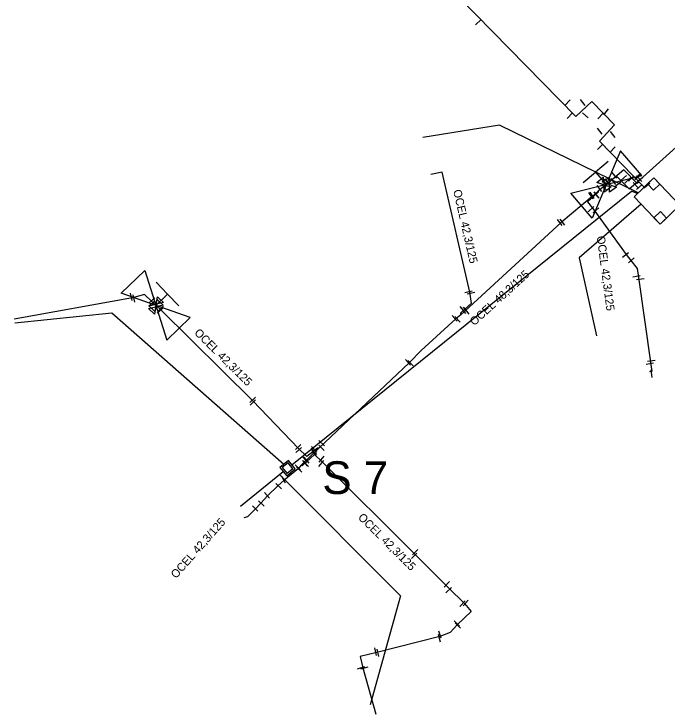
# Model space of a CAD drawing. Extents: x -642943 to -623314, y -1138561 to -1113539.
# Drawn here: x -642363.4 to -642303.4, y -1114769.7 to -1114705.5 of the extents above; entities that cross this region are included whole.
import ezdxf

# ---------------------------------------------------------------- set-up
doc = ezdxf.new("R2010")
doc.units = 0
for name, color, linetype in [('horkovod armatury', 7, 'Continuous'), ('horkovod dimenze', 7, 'Continuous'), ('horkovod předisol', 7, 'Continuous'), ('horkovod sváry', 7, 'Continuous'), ('horkovod trasa', 7, 'Continuous'), ('horkovod zrušený', 7, 'Continuous'), ('horkovod číslo šachty', 7, 'Continuous'), ('horkovod šachty', 7, 'Continuous')]:
    doc.layers.add(name, color=color, linetype=linetype)

# ---------------------------------------------------------------- blocks, each defined once
blk = doc.blocks.new('SPH_2')
at = {"layer": 'horkovod sváry'}
blk.add_line((-0.0001, -0.0349), (0.0001, 0.0349), dxfattribs=at)
blk = doc.blocks.new('SPH_1')
at = {"layer": 'horkovod sváry'}
blk.add_line((0.0001, -0.035), (-0.0001, 0.035), dxfattribs=at)
blk = doc.blocks.new('SPH')
at = {"layer": 'horkovod sváry'}
blk.add_line((0, -0.035), (0, 0.035), dxfattribs=at)
blk = doc.blocks.new('POINT_DISPLAY')
blk.add_line((0, 0), (0, 0))
blk = doc.blocks.new('SH')
at = {"layer": 'horkovod armatury'}
for p, q in [((-0.0568, -0.0385), (-0.0564, 0.0379)), ((-0.0564, 0.0379), (0, 0)), ((0.0007, -0.0004), (0.0582, 0.0375)), ((0.0582, 0.0375), (0.0581, -0.0389)), ((0.0007, -0.0004), (-0.0568, -0.0385)), ((0.0581, -0.0389), (0.0007, -0.0004))]:
    blk.add_line(p, q, dxfattribs=at)
blk = doc.blocks.new('SCH_01_109')
at = {"layer": 'horkovod armatury'}
for p, q in [((10, 5), (-10, -5)), ((-10, -5), (-10, 5)), ((-10, 5), (10, -5)), ((-5, 5), (0, 5)), ((0, 5), (0, 0)), ((5, 5), (0, 5)), ((10, -5), (10, 5))]:
    blk.add_line(p, q, dxfattribs=at)

msp = doc.modelspace()

# ---------------------------------------------------------------- linework, layer by layer
at = {"layer": 'horkovod předisol'}
for p, q in [((-642335.423, -1114690.871), (-642311.877, -1114714.932)), ((-642310.439, -1114713.537), (-642311.877, -1114714.932)), ((-642310.439, -1114713.537), (-642308.35, -1114715.667)), ((-642308.35, -1114715.667), (-642309.71, -1114717.178)), ((-642309.71, -1114717.178), (-642305.643, -1114721.406)), ((-642335.418, -1114745.319), (-642337.045, -1114746.875))]:
    msp.add_line(p, q, dxfattribs=at)
for points in [[(-642308.17, -1114720.391), (-642306.992, -1114721.546), (-642305.755, -1114720.476), (-642302.077, -1114717.169), (-642301.275, -1114716.574), (-642300.333, -1114716.204), (-642298.928, -1114715.605), (-642292.818, -1114713.4)], [(-642322.435, -1114733.08), (-642322.435, -1114732.922), (-642321.439, -1114732.033), (-642321.608, -1114731.022), (-642324.13, -1114720.017), (-642325.177, -1114720.242)], [(-642306.107, -1114720.923), (-642306.271, -1114721.062), (-642307.489, -1114719.816), (-642308.919, -1114721.023), (-642309.354, -1114721.357), (-642309.837, -1114721.774)], [(-642309.837, -1114721.774), (-642310.397, -1114722.253), (-642313.246, -1114724.635), (-642322.435, -1114733.08)], [(-642309.837, -1114721.774), (-642309.848, -1114721.858), (-642310.827, -1114722.742), (-642310.249, -1114723.479), (-642307.277, -1114727.559), (-642306.845, -1114728.129), (-642306.263, -1114728.839), (-642306.148, -1114729.669), (-642305.04, -1114737.434), (-642304.919, -1114738.282), (-642305.151, -1114738.315)], [(-642335.418, -1114745.319), (-642335.547, -1114745.319), (-642336.534, -1114746.077), (-642337.306, -1114745.334), (-642341.49, -1114740.989), (-642349.936, -1114732.617), (-642350.735, -1114731.885), (-642351.395, -1114731.233), (-642352.496, -1114731.53), (-642363.352, -1114733.479)], [(-642322.435, -1114733.08), (-642322.887, -1114733.472), (-642326.048, -1114736.35), (-642327.142, -1114737.495), (-642335.418, -1114745.319)], [(-642337.045, -1114746.875), (-642336.938, -1114746.893), (-642335.831, -1114745.901), (-642335.162, -1114746.535), (-642326.636, -1114755.033), (-642323.54, -1114758.119), (-642322.101, -1114759.553), (-642321.476, -1114760.281), (-642322.736, -1114761.475), (-642323.406, -1114762.221), (-642324.343, -1114762.58), (-642330.13, -1114764.032), (-642331.637, -1114764.412), (-642331.393, -1114765.439), (-642330.208, -1114769.678)], [(-642337.045, -1114746.875), (-642337.285, -1114747.182), (-642338.629, -1114748.271), (-642339.162, -1114748.745), (-642340.122, -1114749.694), (-642340.736, -1114750.343), (-642341.218, -1114750.873), (-642341.953, -1114751.6), (-642342.307, -1114751.702)]]:
    msp.add_lwpolyline(points, dxfattribs=at)
at = {"layer": 'horkovod trasa'}
for p, q in [((-642335.423, -1114690.871), (-642311.877, -1114714.932)), ((-642310.439, -1114713.537), (-642311.877, -1114714.932)), ((-642310.439, -1114713.537), (-642308.35, -1114715.667)), ((-642308.35, -1114715.667), (-642309.71, -1114717.178)), ((-642309.71, -1114717.178), (-642305.643, -1114721.406)), ((-642335.418, -1114745.319), (-642337.045, -1114746.875))]:
    msp.add_line(p, q, dxfattribs=at)
for points in [[(-642308.17, -1114720.391), (-642306.992, -1114721.546), (-642305.755, -1114720.476), (-642302.077, -1114717.169), (-642301.275, -1114716.574), (-642300.333, -1114716.204), (-642298.928, -1114715.605), (-642292.818, -1114713.4)], [(-642322.435, -1114733.08), (-642322.435, -1114732.922), (-642321.439, -1114732.033), (-642321.608, -1114731.022), (-642324.13, -1114720.017), (-642325.177, -1114720.242)], [(-642306.107, -1114720.923), (-642306.271, -1114721.062), (-642307.489, -1114719.816), (-642308.919, -1114721.023), (-642309.354, -1114721.357), (-642309.837, -1114721.774)], [(-642309.837, -1114721.774), (-642310.397, -1114722.253), (-642313.246, -1114724.635), (-642322.435, -1114733.08)], [(-642309.837, -1114721.774), (-642309.848, -1114721.858), (-642310.827, -1114722.742), (-642310.249, -1114723.479), (-642307.277, -1114727.559), (-642306.845, -1114728.129), (-642306.263, -1114728.839), (-642306.148, -1114729.669), (-642305.04, -1114737.434), (-642304.919, -1114738.282), (-642305.151, -1114738.315)], [(-642335.418, -1114745.319), (-642335.547, -1114745.319), (-642336.534, -1114746.077), (-642337.306, -1114745.334), (-642341.49, -1114740.989), (-642349.936, -1114732.617), (-642350.735, -1114731.885), (-642351.395, -1114731.233), (-642352.496, -1114731.53), (-642363.352, -1114733.479)], [(-642322.435, -1114733.08), (-642322.887, -1114733.472), (-642326.048, -1114736.35), (-642327.142, -1114737.495), (-642335.418, -1114745.319)], [(-642337.045, -1114746.875), (-642336.938, -1114746.893), (-642335.831, -1114745.901), (-642335.162, -1114746.535), (-642326.636, -1114755.033), (-642323.54, -1114758.119), (-642322.101, -1114759.553), (-642321.476, -1114760.281), (-642322.736, -1114761.475), (-642323.406, -1114762.221), (-642324.343, -1114762.58), (-642330.13, -1114764.032), (-642331.637, -1114764.412), (-642331.393, -1114765.439), (-642330.208, -1114769.678)], [(-642337.045, -1114746.875), (-642337.285, -1114747.182), (-642338.629, -1114748.271), (-642339.162, -1114748.745), (-642340.122, -1114749.694), (-642340.736, -1114750.343), (-642341.218, -1114750.873), (-642341.953, -1114751.6), (-642342.307, -1114751.702)]]:
    msp.add_lwpolyline(points, dxfattribs=at)
at = {"layer": 'horkovod zrušený'}
for p, q in [((-642318.867, -1114715.712), (-642325.9, -1114716.855)), ((-642306.191, -1114721.924), (-642318.867, -1114715.712)), ((-642337.91, -1114746.834), (-642306.789, -1114721.749)), ((-642306.257, -1114721.988), (-642306.789, -1114721.749)), ((-642342.614, -1114750.633), (-642338.685, -1114747.465)), ((-642327.936, -1114758.86), (-642339.028, -1114747.742)), ((-642327.936, -1114758.86), (-642330.721, -1114768.834))]:
    msp.add_line(p, q, dxfattribs=at)
for points in [[(-642305.918, -1114722.952), (-642311.597, -1114727.865), (-642309.985, -1114735.005)], [(-642363.268, -1114733.835), (-642354.383, -1114732.908), (-642338.63, -1114746.776)]]:
    msp.add_lwpolyline(points, dxfattribs=at)
at = {"layer": 'horkovod šachty'}
for p, q in [((-642304.735, -1114720.547), (-642305.316, -1114721.097)), ((-642304.185, -1114721.128), (-642304.735, -1114720.547)), ((-642305.316, -1114721.097), (-642304.766, -1114721.678)), ((-642304.766, -1114721.678), (-642304.185, -1114721.128)), ((-642304.15, -1114723.639), (-642304.731, -1114724.191)), ((-642303.599, -1114724.22), (-642304.15, -1114723.639)), ((-642304.731, -1114724.191), (-642304.179, -1114724.771)), ((-642303.599, -1114724.22), (-642304.179, -1114724.771)), ((-642338.24, -1114746.656), (-642338.784, -1114747.096)), ((-642337.8, -1114747.2), (-642338.24, -1114746.656)), ((-642338.784, -1114747.096), (-642338.344, -1114747.64)), ((-642337.8, -1114747.2), (-642338.344, -1114747.64))]:
    msp.add_line(p, q, dxfattribs=at)
for points in [[(-642306.551, -1114722.266), (-642304.179, -1114724.771), (-642302.363, -1114723.052), (-642304.735, -1114720.547), (-642306.551, -1114722.266)], [(-642339.002, -1114747.073), (-642338.374, -1114747.851), (-642337.596, -1114747.223), (-642338.224, -1114746.445), (-642339.002, -1114747.073)]]:
    msp.add_lwpolyline(points, dxfattribs=at)

# ---------------------------------------------------------------- block references
at = {"layer": 'horkovod armatury'}
for name, p, xscale, yscale, rotation in [('SCH_01_109', (-642309.102, -1114721.144), 0.29998715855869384, 0.29998715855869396, 40.60257967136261), ('SH', (-642309.32, -1114721.16), 9.9999986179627, 9.9999986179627, -50.46904901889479), ('SH', (-642308.82, -1114721.15), 10.000000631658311, 10.000000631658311, -54.431741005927), ('SCH_01_109', (-642350.362, -1114732.228), 0.2999871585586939, 0.2999871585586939, -46.15509971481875), ('SH', (-642350.331, -1114732.117), 10.000000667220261, 10.00000066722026, 45.99239812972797), ('SH', (-642350.37, -1114732.37), 10.000013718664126, 10.000013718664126, 47.00510154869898)]:
    msp.add_blockref(name, p, dxfattribs=dict(at, xscale=xscale, yscale=yscale, rotation=rotation))
at = {"layer": 'horkovod sváry'}
for name, p, xscale, yscale, rotation in [('SPH_2', (-642320.83, -1114706.27), 10.000023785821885, 10.000023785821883, -46.93544318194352), ('SPH_2', (-642312.66, -1114713.65), 10.000015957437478, 10.000015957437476, -44.32590539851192), ('SPH_2', (-642311.25, -1114713.64), 9.99998312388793, 9.99998312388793, 38.360172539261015), ('SPH_2', (-642309.11, -1114714.48), 9.99999901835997, 9.999999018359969, -38.7285186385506), ('SPH_2', (-642312.44, -1114714.84), 10.00001530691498, 10.00001530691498, -41.54185407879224), ('SPH_2', (-642311.02, -1114714.81), 10.000009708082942, 10.000009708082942, 47.55888123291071), ('SPH_1', (-642309.63, -1114714.86), 9.999987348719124, 9.999987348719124, -42.8482080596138), ('SPH_2', (-642309.69, -1114716.26), 9.999994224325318, 9.999994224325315, 38.69947611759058), ('SPH', (-642308.5, -1114716.58), 9.999973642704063, 9.999973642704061, 38.324837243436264), ('SPH_2', (-642309.67, -1114717.69), 10.000012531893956, 10.000012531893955, -44.709086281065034), ('SPH_1', (-642308.53, -1114717.95), 10.000004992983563, 10.000004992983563, -42.79100666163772), ('SPH_2', (-642308.35, -1114720.3), 9.999996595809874, 9.999996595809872, 40.754295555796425), ('SPH_2', (-642309.01, -1114720.91), 9.999967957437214, 9.999967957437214, 38.46784328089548), ('SPH_2', (-642308.45, -1114720.87), 9.999978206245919, 9.999978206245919, 38.945776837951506), ('SPH_2', (-642307.51, -1114720.55), 10.00001452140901, 10.00001452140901, -49.06486324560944), ('SPH_1', (-642307.15, -1114720.79), 10.00000385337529, 10.000003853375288, -47.21371358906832), ('SPH_2', (-642306.82, -1114720.61), 9.999989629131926, 9.999989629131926, -45.39505637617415), ('SPH_2', (-642306.22, -1114720.36), 10.000015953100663, 10.000015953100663, -48.83774303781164), ('SPH_2', (-642306.22, -1114720.48), 10.000005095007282, 10.00000509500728, -48.71069255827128), ('SPH_2', (-642306.1, -1114720.62), 9.999991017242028, 9.999991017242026, 44.06703707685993), ('SPH_2', (-642309.72, -1114721.52), 10.000023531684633, 10.000023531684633, 37.016746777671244), ('SPH_2', (-642309.28, -1114721.44), 10.000001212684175, 10.000001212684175, 39.95495661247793), ('SPH_2', (-642308.04, -1114721.12), 10.000005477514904, 10.000005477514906, -49.21827027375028), ('SPH', (-642306.4, -1114721.23), 9.999984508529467, 9.999984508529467, 42.14080740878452), ('SPH_2', (-642306.07, -1114721.39), 9.99999073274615, 9.99999073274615, -48.4993581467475), ('SPH_2', (-642305.38, -1114721.25), 10.000020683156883, 10.000020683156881, -48.15446315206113), ('SPH', (-642310.5, -1114722.17), 9.999991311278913, 9.999991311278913, 33.90111137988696), ('SPH_2', (-642310.39, -1114722.15), 9.999998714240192, 9.999998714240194, 32.89885229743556), ('SPH_2', (-642310, -1114722.11), 9.999985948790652, 9.999985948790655, 37.971603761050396), ('SPH_2', (-642309.97, -1114722.14), 9.999987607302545, 9.999987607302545, 39.00819611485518), ('SPH_2', (-642310.5, -1114723.41), 10.00000497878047, 10.000004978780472, -46.81690519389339), ('SPH_1', (-642310.05, -1114723.52), 9.999983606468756, 9.999983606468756, -49.64630891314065), ('SPH_2', (-642313.35, -1114724.64), 9.999985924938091, 9.999985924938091, 39.94737309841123), ('SPH_2', (-642313.11, -1114724.61), 9.999981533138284, 9.999981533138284, 39.52999399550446), ('SPH_2', (-642307.33, -1114727.6), 10.00001117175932, 10.00001117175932, -50.95138605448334), ('SPH_1', (-642306.81, -1114728.1), 9.999997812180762, 9.999997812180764, -50.932426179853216), ('SPH_2', (-642306.34, -1114729.54), 9.999991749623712, 9.999991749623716, -80.1902849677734), ('SPH_2', (-642305.99, -1114729.81), 10.000014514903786, 10.000014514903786, -81.77986946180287), ('SPH_2', (-642321.72, -1114730.98), 9.999999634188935, 9.999999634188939, -76.87367718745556), ('SPH_2', (-642352.61, -1114731.44), 10.000004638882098, 10.000004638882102, 11.242852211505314), ('SPH_2', (-642352.36, -1114731.6), 10.000014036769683, 10.000014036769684, 12.171437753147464), ('SPH_1', (-642350.72, -1114731.77), 9.999984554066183, 9.999984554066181, -48.11271832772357), ('SPH_2', (-642321.49, -1114731.1), 9.999983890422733, 9.999983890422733, -77.93740603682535), ('SPH_2', (-642350.73, -1114732.03), 10.000009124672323, 10.00000912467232, -48.85684328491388), ('SPH_2', (-642349.99, -1114732.72), 9.999990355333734, 9.999990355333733, -47.60251080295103), ('SPH_2', (-642349.9, -1114732.52), 10.000007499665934, 10.000007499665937, -46.4237694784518), ('SPH_1', (-642322.26, -1114732.6), 10.000021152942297, 10.000021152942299, 39.28946317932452), ('SPH_2', (-642322.19, -1114732.7), 9.99999825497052, 9.999998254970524, 38.36758997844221), ('SPH_2', (-642321.97, -1114732.65), 9.999991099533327, 9.999991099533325, 38.77747858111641), ('SPH_2', (-642321.88, -1114732.75), 9.9999906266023, 9.999990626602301, 38.422092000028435), ('SPH_1', (-642322.99, -1114733.42), 10.000014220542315, 10.000014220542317, 42.81423085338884), ('SPH_2', (-642322.74, -1114733.5), 10.00000659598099, 10.000006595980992, 43.780980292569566), ('SPH_1', (-642327.27, -1114737.46), 10.000000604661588, 10.000000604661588, 42.5370475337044), ('SPH_2', (-642327.02, -1114737.52), 10.000009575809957, 10.000009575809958, 44.47344463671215), ('SPH_2', (-642304.98, -1114737.286), 10.000014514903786, 10.000014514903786, -81.77986946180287), ('SPH_2', (-642305.118, -1114737.561), 9.999991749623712, 9.999991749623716, -80.1902849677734), ('SPH_2', (-642304.969, -1114738.491), 9.999996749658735, 9.999996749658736, -170.8897638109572), ('SPH_2', (-642341.49, -1114740.88), 9.999984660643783, 9.999984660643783, -45.39090596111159), ('SPH_2', (-642341.47, -1114741.12), 9.999987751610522, 9.999987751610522, -44.02288427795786), ('SPH_2', (-642337.32, -1114745.21), 9.999991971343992, 9.99999197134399, -46.39716262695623), ('SPH_2', (-642335.18, -1114745.27), 10.00000694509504, 10.000006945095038, 45.915225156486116), ('SPH_2', (-642335.16, -1114744.86), 9.999999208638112, 9.999999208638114, 47.93550435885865), ('SPH_2', (-642337.28, -1114745.49), 10.000002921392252, 10.000002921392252, -47.950615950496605), ('SPH_2', (-642335.89, -1114745.57), 10.000000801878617, 10.000000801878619, 43.32635303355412), ('SPH_2', (-642335.88, -1114745.7), 10.000000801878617, 10.000000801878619, 43.32635303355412), ('SPH_2', (-642335.86, -1114745.43), 10.000019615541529, 10.000019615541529, 41.91147635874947), ('SPH', (-642335.83, -1114745.88), 9.999996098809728, 9.999996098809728, 42.8619917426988), ('SPH_2', (-642336.69, -1114746.32), 10.000019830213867, 10.000019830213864, 40.507387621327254), ('SPH_1', (-642336.55, -1114746.41), 10.000001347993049, 10.000001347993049, 40.601236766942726), ('SPH_2', (-642335.16, -1114746.32), 9.999988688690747, 9.999988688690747, -40.958578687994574), ('SPH_2', (-642337.35, -1114747.09), 9.999979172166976, 9.999979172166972, 44.8603915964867), ('SPH_1', (-642336.7, -1114746.69), 10.000018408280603, 10.000018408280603, 41.8595179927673), ('SPH_1', (-642336.628, -1114746.741), 10.000004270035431, 10.000004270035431, 42.211268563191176), ('SPH_2', (-642335.19, -1114746.72), 9.999978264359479, 9.99997826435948, -40.75826050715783), ('SPH_2', (-642337.22, -1114747.26), 10.000001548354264, 10.000001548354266, 44.569286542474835), ('SPH_2', (-642338.656, -1114748.218), 10.000015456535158, 10.00001545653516, 27.44684979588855), ('SPH_2', (-642339.11, -1114748.8), 10.000002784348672, 10.000002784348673, 44.884351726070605), ('SPH_2', (-642340.18, -1114749.63), 10.000002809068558, 10.000002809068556, 42.43356307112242), ('SPH_2', (-642340.7, -1114750.38), 10.00000446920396, 10.000004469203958, 45.563157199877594), ('SPH_2', (-642341.25, -1114750.84), 9.99999157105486, 9.99999157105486, 45.07753911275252), ('SPH_2', (-642326.61, -1114754.84), 9.999995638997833, 9.999995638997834, -44.573814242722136), ('SPH_2', (-642326.69, -1114755.19), 9.99999685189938, 9.999996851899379, -43.774751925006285), ('SPH_2', (-642323.7, -1114757.79), 9.99999135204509, 9.99999135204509, -43.87759232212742), ('SPH_2', (-642323.53, -1114758.32), 9.999996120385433, 9.999996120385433, -46.302051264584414), ('SPH', (-642322.27, -1114759.58), 9.99999856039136, 9.999998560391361, -42.07564092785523), ('SPH_2', (-642321.98, -1114759.51), 9.999974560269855, 9.999974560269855, -43.37749663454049), ('SPH_2', (-642322.79, -1114761.38), 10.000014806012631, 10.000014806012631, 44.85416632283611), ('SPH_2', (-642322.69, -1114761.57), 10.000025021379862, 10.000025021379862, 45.61145527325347), ('SPH_2', (-642324.32, -1114762.41), 9.99998418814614, 9.99998418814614, 18.044982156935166), ('SPH_2', (-642324.38, -1114762.74), 9.999998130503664, 9.999998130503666, 13.708098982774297), ('SPH_1', (-642330.23, -1114763.97), 9.999987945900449, 9.999987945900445, 10.982115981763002), ('SPH_2', (-642330.02, -1114764.08), 10.00001361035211, 10.000013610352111, 13.549945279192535), ('SPH_2', (-642331.55, -1114765.43), 10.000001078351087, 10.000001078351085, -74.29886670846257), ('SPH_1', (-642331.25, -1114765.46), 10.000014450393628, 10.000014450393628, -74.78000513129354)]:
    msp.add_blockref(name, p, dxfattribs=dict(at, xscale=xscale, yscale=yscale, rotation=rotation))
at = {"layer": 'horkovod šachty'}
for p in [(-642304.75, -1114721.112), (-642304.165, -1114724.206), (-642338.299, -1114747.148)]:
    msp.add_blockref('POINT_DISPLAY', p, dxfattribs=at)

# ---------------------------------------------------------------- texts
at = {"layer": 'horkovod dimenze'}
for s, height, rotation, p in [('OCEL 42,3/125', 0.75, 282.90832, (-642323.131, -1114721.703)), ('OCEL 42,3/125', 0.75, 277.56143, (-642309.979, -1114725.915)), ('OCEL 48,3/125', 0.74999, 42.35746, (-642321.188, -1114734.14)), ('OCEL 42,3/125', 0.75, 315.17083, (-642346.893, -1114734.804)), ('OCEL 42,3/125', 0.75, 315.10069, (-642331.895, -1114751.724)), ('OCEL 42,3/125', 0.75, 48.51375, (-642348.506, -1114757.313))]:
    msp.add_text(s, height=height, rotation=rotation, dxfattribs=at).set_placement(p)
at = {"layer": 'horkovod číslo šachty'}
msp.add_text('S 7', height=3, dxfattribs=at).set_placement((-642335.104, -1114749.518))

doc.saveas('drawing.dxf')
